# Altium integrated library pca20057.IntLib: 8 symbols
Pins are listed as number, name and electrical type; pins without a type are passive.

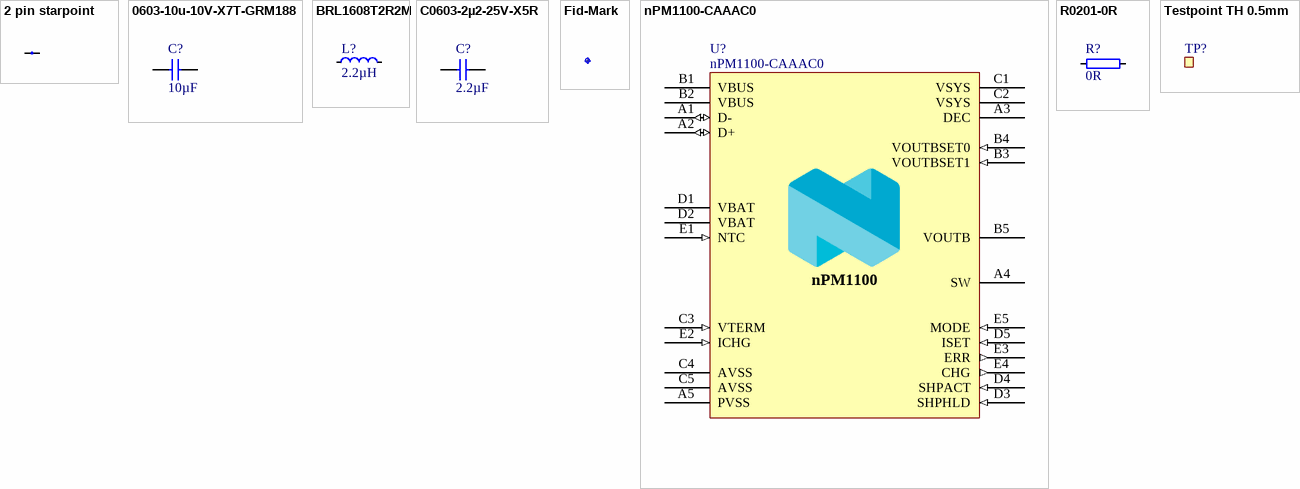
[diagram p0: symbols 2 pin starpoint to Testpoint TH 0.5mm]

## 2 pin starpoint
designator J?, comment N.A.  (value not drawn)  (net tie, no BOM)
Starpoint; Part Number: 2 pin starpoint; Pad Count: 2
footprint 2 PIN STARPOINT
pins: 1, 2

## 0603-10u-10V-X7T-GRM188
designator C?, comment 10µF
CAP CER 10UF 10V X7T 0603; Part Number: 0603-10u-10V-X7T-GRM188; Manufacturer: Murata; Manufacturer Part Number: GRM188D71A106MA73; Part number IPS: 00000004696; Note: 10VDC; Artikkelnr Noca: N.A.; Pad Count: 2
footprint CAPC1608X06L
pins: 1, 2

## BRL1608T2R2M
designator L?, comment 2.2µH
FIXED IND 2.2UH 500MA 520 MOHM; Part Number: BRL1608T2R2M; Manufacturer: Taiyo Yuden; Pad Count: 2; Note: -40°C ~ 105°C; Artikkelnr Noca: N.A.
footprint INDC1608X06L
pins: 1, 2

## C0603-2µ2-25V-X5R
designator C?, comment 2.2µF
Capacitor, Ceramic, X5R, ±10%, 25V; Part Number: C0603-2µ2-25V-X5R; Manufacturer: Murata; Manufacturer Part Number: GRM188R61E225KA12D; Pad Count: 2; Artikkelnr Noca: N.A.
footprint CAPC1608X06L
pins: 1, 2

## Fid-Mark
designator Fid?, comment Fiducial mark  (value not drawn)
Part Number: Fid-Mark; Artikkelnr Noca: N.A.; Pad Count: 1
footprint Fiducial

## nPM1100-CAAAC0
designator U?
Li-Ion/Li-Polymer USB battery charger with a high efficiency buck regulator; Manufacturer: Nordic Semiconductor; Note: N.A.; Pad Count: 25
footprint BGA25C40P5X5_200X200X50
pins: A1 D- (io), A2 D+ (io), A3 DEC (power), A4 SW (power), A5 PVSS (power), B1 VBUS (power), B2 VBUS (power), B3 VOUTBSET1 (in), B4 VOUTBSET0 (in), B5 VOUTB (power), C1 VSYS (power), C2 VSYS (power), C3 VTERM (in), C4 AVSS (power), C5 AVSS (power), D1 VBAT (power), D2 VBAT (power), D3 SHPHLD (in), D4 SHPACT (in), D5 ISET (in), E1 NTC (in), E2 ICHG (in), E3 ERR (out), E4 CHG (out), E5 MODE (in)

## R0201-0R
designator R?, comment 0R
Resistor, ±5%, 0.05W; Part Number: R0201-0R; Manufacturer: N.A.; Part number IPS: 00000003245; Pad Count: 2; Note: Chip Res 5%
footprint RESC0603X03L_C
pins: 1, 2

## Testpoint TH 0.5mm
designator TP?, comment TP  (value not drawn)  (no BOM)
Testpoint, through hole; Part Number: Testpoint TH 0.5mm; Manufacturer: N.A.; Pad Count: 1
footprint TESTPAD-TH - 0.5mm
pins: 1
